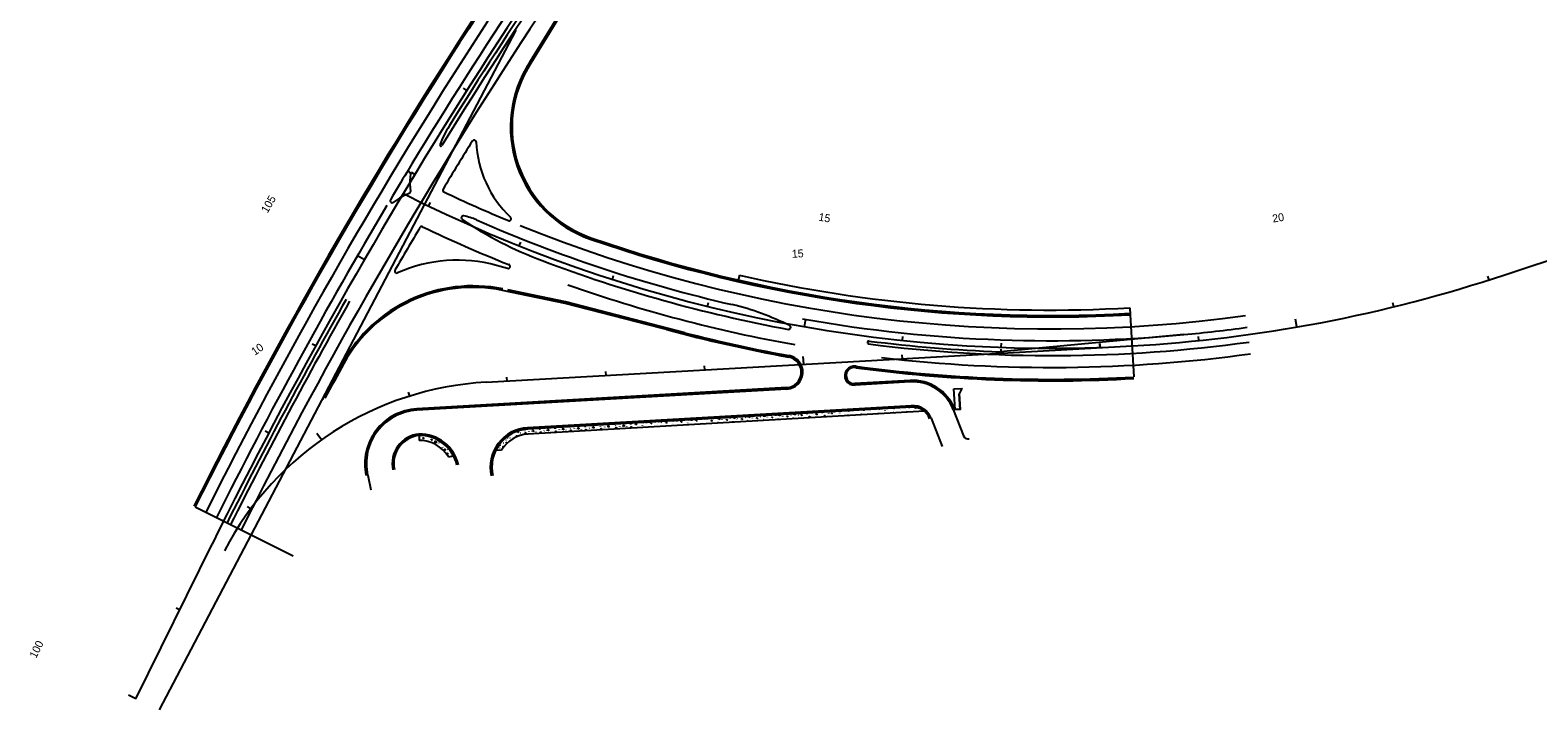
# Model space of a CAD drawing. Extents: x 2339272 to 2351734, y 366540 to 375057.
# Drawn here: x 2345285 to 2346808, y 366762 to 367449 of the extents above; entities that cross this region are included whole.
import ezdxf

# ---------------------------------------------------------------- set-up
doc = ezdxf.new("R2010")
doc.units = 0
for name, color, linetype in [('RD_HC_Cl', 7, 'Continuous'), ('RD_HC_CL_Rel', 7, 'Continuous'), ('RD_HC_Data_Tic', 7, 'Continuous'), ('RD_HC_Data_Tic_Rel', 7, 'Continuous'), ('RD_HC_TX_Rel_Sta50', 7, 'Continuous'), ('RD_HC_TX_Sta50', 7, 'Continuous'), ('RD_PD_Final_LnLine', 7, 'Continuous'), ('RD_PD_Final_TrvlWay', 7, 'Continuous'), ('RD_PD_FOC', 7, 'Continuous'), ('RD_PD_SW', 7, 'Continuous')]:
    doc.layers.add(name, color=color, linetype=linetype)

msp = doc.modelspace()

# ---------------------------------------------------------------- linework, layer by layer
at = {"layer": 'RD_HC_Cl'}
for p, q in [((2345775.2, 367448.5), (2345415, 366761.9)), ((2345775.2, 367448.5), (2345415, 366761.9)), ((2345775.2, 367448.5), (2345415, 366761.9)), ((2345775.2, 367448.5), (2345415, 366761.9)), ((2346774.2, 367201.5), (2347080, 367303.2)), ((2345745.3, 367092.9), (2346397.7, 367129.6)), ((2345391.2, 366773.2), (2345468.3, 366929.3))]:
    msp.add_line(p, q, dxfattribs=at)
for centre, radius, start, end in [((2349947, 364715.5), 4996, 141.0938, 153.6971), ((2346316.3, 368577.7), 1450.4, 273.2156, 288.4001), ((2345763.2, 366774.4), 319, 93.2156, 152.2947)]:
    msp.add_arc(centre, radius, start, end, dxfattribs=at)
at = {"layer": 'RD_HC_CL_Rel'}
msp.add_arc((2346316.3, 368577.7), 1450.4, 243.1643, 273.2156, dxfattribs=at)
at = {"layer": 'RD_HC_Data_Tic'}
for p, q in [((2345725.7, 367387.6), (2345722.3, 367389.8)), ((2345673.1, 367302.6), (2345669.7, 367304.7)), ((2345622.2, 367216.5), (2345615.2, 367220.6)), ((2346758.4, 367196.3), (2346757.1, 367200.1)), ((2346662.1, 367169.1), (2346661.2, 367173)), ((2346564.3, 367148.7), (2346562.9, 367156.5)), ((2346465.2, 367135), (2346464.8, 367139)), ((2345573, 367129.5), (2345569.5, 367131.4)), ((2346265.7, 367122.2), (2346265.4, 367126.2)), ((2346365.5, 367127.8), (2346365.3, 367131.8)), ((2345966.1, 367105.4), (2345965.9, 367109.4)), ((2346066, 367111), (2346065.5, 367119)), ((2346165.8, 367116.6), (2346165.6, 367120.6)), ((2345766.5, 367094.1), (2345766.2, 367098.1)), ((2345866.3, 367099.7), (2345866.1, 367103.7)), ((2345668, 367078.9), (2345666.8, 367082.7)), ((2345525.5, 367041.5), (2345522, 367043.3)), ((2345578.7, 367034.7), (2345574.1, 367041.2)), ((2345507.4, 366965.1), (2345504.2, 366967.5)), ((2345479.9, 366952.5), (2345476.3, 366954.3)), ((2345435.5, 366862.9), (2345431.9, 366864.7)), ((2345391.2, 366773.2), (2345384, 366776.8))]:
    msp.add_line(p, q, dxfattribs=at)
at = {"layer": 'RD_HC_Data_Tic_Rel'}
for p, q in [((2345687.1, 367270.9), (2345688.9, 367274.5)), ((2345778.6, 367230.7), (2345780.1, 367234.4)), ((2345872.7, 367196.8), (2345873.9, 367200.6)), ((2345968.9, 367169.5), (2345969.9, 367173.4)), ((2346066.7, 367149), (2346068.1, 367156.8)), ((2346165.8, 367135.2), (2346166.2, 367139.1)), ((2346265.5, 367128.2), (2346265.7, 367132.2)), ((2346365.5, 367128.2), (2346365.4, 367132.1))]:
    msp.add_line(p, q, dxfattribs=at)
at = {"layer": 'RD_PD_Final_LnLine'}
for p, q in [((2345789.2, 367416.2), (2345867.8, 367544)), ((2345825.4, 367174), (2345767, 367186.1)), ((2345945.8, 367142.9), (2345825.4, 367174)), ((2346173.5, 367093.2), (2346117.9, 367090)), ((2346049.1, 367086), (2345675.1, 367064.5)), ((2346174.9, 367069.2), (2345787.1, 367046.9)), ((2346217, 367065.3), (2346227.4, 367038.7)), ((2346194.7, 367056.6), (2346205.9, 367027.9)), ((2345625.5, 366999.1), (2345628.7, 366984.3)), ((2345550.2, 366917.3), (2345451.2, 366966.8))]:
    msp.add_line(p, q, dxfattribs=at)
for points in [[(2345668.7, 367303.5), (2345668.2, 367296.8), (2345668.1, 367293.1), (2345668.3, 367289.4), (2345668.7, 367285.7)], [(2345667.5, 367283.6), (2345664.3, 367282.3), (2345660.9, 367280.7), (2345657.7, 367278.9), (2345654.5, 367276.9), (2345651.4, 367274.6)]]:
    msp.add_lwpolyline(points, dxfattribs=at)
for centre, radius, start, end in [((2349947, 364715.5), 5028, 141.0938, 153.3996), ((2349947, 364715.5), 5016, 141.0938, 153.4055), ((2349947, 364715.5), 4976, 141.0938, 153.4002), ((2349947, 364715.5), 5004, 144.1409, 148.8707), ((2345889.8, 367350.8), 120, 146.9941, 250.83), ((2349947, 364715.5), 5004, 149.2865, 153.4055), ((2346316.3, 368577.7), 1430.9, 247.9629, 277.8677), ((2346316.3, 368577.7), 1418.9, 250.83, 273.2156), ((2345731.6, 367040.2), 150, 78.3222, 151.1242), ((2346316.3, 368577.7), 1469.9, 250.5817, 259.838), ((2346316.3, 368577.7), 1442.9, 259.9604, 267.9572), ((2346316.3, 368577.7), 1481.9, 254.8096, 259.6918), ((2346316.3, 368577.7), 1442.9, 267.9572, 275.3139), ((2349947, 364715.5), 4964, 151.1242, 151.6138), ((2346048.1, 367103), 17, 273.295, 79.6918), ((2346117, 367099.6), 9.61, 79.003, 275.1081), ((2346316.3, 368577.7), 1481.9, 262.3405, 273.2156), ((2346316.3, 368577.7), 1469.9, 263.2921, 277.8677), ((2346176, 367049.3), 44, 21.3855, 93.295), ((2345678.2, 367010.6), 54, 93.295, 192.3286), ((2346176, 367049.3), 20, 21.3855, 93.295), ((2345680.3, 367010.7), 30, 95.7625, 192.3286), ((2345678.1, 367000.6), 40, 12.6698, 91.1581), ((2345789.4, 367007), 40, 93.295, 192.6698)]:
    msp.add_arc(centre, radius, start, end, dxfattribs=at)
at = {"layer": 'RD_PD_Final_TrvlWay'}
for p, q in [((2345766.8, 367207.9), (2345755.8, 367210.9)), ((2346395.9, 367161.1), (2346399.5, 367098.2)), ((2346450, 367141), (2346264.3, 367123.7))]:
    msp.add_line(p, q, dxfattribs=at)
for centre, radius, start, end in [((2349947, 364715.5), 4992, 144.1121, 148.1246), ((2349947, 364715.5), 4988, 144.1121, 148.3622), ((2345792.4, 367298.2), 100, 147.742, 159.7908), ((2349947, 364715.5), 4964, 148.1282, 148.7856), ((2345733.1, 367335.5), 2, 2.3688, 148.1282), ((2345699.5, 367332.4), 1, 159.7908, 328.3622), ((2345846.1, 367340.2), 111, 182.3688, 226.6168), ((2349947, 364715.5), 5004, 148.84, 149.2061), ((2345666.7, 367303.6), 2, 355.4391, 148.84), ((2345650.2, 367276.2), 2, 149.2061, 306.5069), ((2345666.7, 367285.4), 2, 291.356, 6.6707), ((2345703.4, 367287), 2, 148.7856, 244.5967), ((2346316.3, 368577.7), 1430.9, 244.5967, 247.4525), ((2345722.1, 367259), 2, 79.0993, 236.2521), ((2345711.2, 367202), 60, 66.255, 79.0993), ((2349947, 364715.5), 4964, 149.3076, 149.8844), ((2345680.1, 367248.2), 2, 64.4267, 149.3076), ((2346316.3, 368577.7), 1471.9, 244.4267, 248.1316), ((2345943.2, 367589.9), 400, 236.2521, 249.308), ((2346316.3, 368577.7), 1442.9, 246.255, 257.0838), ((2345768.4, 367258), 2, 247.4525, 46.6168), ((2345716.5, 367066.2), 150, 74.8096, 113.9269), ((2346316.3, 368577.7), 1455.9, 249.308, 259.4801), ((2345654.8, 367205.1), 2, 149.8844, 293.9269), ((2345767.4, 367209.9), 2, 254.8096, 68.1316), ((2349947, 364715.5), 4992, 150.4616, 153.4055), ((2349947, 364715.5), 4988, 150.4616, 153.4055), ((2345929.6, 366906.7), 272.3, 63.3299, 76.3521), ((2346050.9, 367148.3), 2, 259.4801, 63.3299), ((2346316.3, 368577.7), 1442.9, 275.3139, 277.8677), ((2346131.8, 367133.1), 1.5, 82.7196, 172.6606), ((2346131.8, 367133.1), 1.5, 172.6606, 262.7196), ((2346316.3, 368577.7), 1457.9, 262.7196, 277.8677), ((2346316.3, 368577.7), 1454.9, 262.7196, 267.9499), ((2346232.1, 367040.5), 5, 201.3855, 282.6674)]:
    msp.add_arc(centre, radius, start, end, dxfattribs=at)
at = {"layer": 'RD_PD_FOC'}
for p, q in [((2345790.5, 367415.4), (2345869, 367543.2)), ((2345825.1, 367172.5), (2345761.6, 367185.6)), ((2345945.5, 367141.4), (2345825, 367172.5)), ((2346173.4, 367094.7), (2346117.8, 367091.5)), ((2346049, 367087.5), (2345675.1, 367066)), ((2346175, 367067.7), (2345787.2, 367045.4))]:
    msp.add_line(p, q, dxfattribs=at)
for centre, radius, start, end in [((2349947, 364715.5), 5029.5, 141.0938, 153.3986), ((2345889.8, 367350.8), 118.5, 146.9941, 250.83), ((2346316.3, 368577.7), 1417.4, 250.83, 273.2155), ((2345731.6, 367040.2), 148.5, 78.3222, 151.1242), ((2346316.3, 368577.7), 1483.4, 254.8096, 259.6918), ((2349947, 364715.5), 4962.5, 151.1242, 151.5864), ((2346048.1, 367103), 15.5, 273.295, 79.6918), ((2346117, 367099.6), 8.11, 79.003, 275.1081), ((2346316.3, 368577.7), 1483.4, 262.3405, 273.2156), ((2346176, 367049.3), 45.5, 21.3855, 93.295), ((2345678.2, 367010.6), 55.5, 93.295, 192.3286), ((2346176, 367049.3), 18.5, 21.3855, 93.295), ((2345680.3, 367010.7), 28.5, 95.7625, 192.3286), ((2345678.1, 367000.6), 38.5, 12.6698, 91.1581), ((2345789.4, 367007), 38.5, 93.295, 192.6698)]:
    msp.add_arc(centre, radius, start, end, dxfattribs=at)
at = {"layer": 'RD_PD_SW'}
for p, q in [((2346001, 367201.1), (2345999.5, 367194.6)), ((2346395.5, 367168.1), (2346395.9, 367161.1)), ((2346217.7, 367086.1), (2346225.7, 367086.5)), ((2346218.9, 367065.3), (2346217.7, 367086.1)), ((2346225.7, 367086.5), (2346223, 367081.1)), ((2346223.9, 367065.5), (2346223, 367081.1)), ((2346187.9, 367063.5), (2345787.4, 367040.4)), ((2346083.8, 367062.1), (2346083.9, 367062.5)), ((2346111, 367063.6), (2346111.1, 367064.1)), ((2346117.7, 367062.6), (2346117.8, 367062.8)), ((2346126.2, 367064.5), (2346126.4, 367064.9)), ((2346133, 367063.5), (2346133.1, 367063.7)), ((2346141.5, 367065.4), (2346141.7, 367065.8)), ((2346148.3, 367064.3), (2346148.3, 367064.6)), ((2346154.3, 367062.7), (2346154.4, 367062.5)), ((2346156.4, 367062.7), (2346156.6, 367062.6)), ((2346156.8, 367066.3), (2346156.9, 367066.7)), ((2346163.5, 367065.2), (2346163.6, 367065.5)), ((2346169.6, 367063.6), (2346169.7, 367063.4)), ((2346171.7, 367063.6), (2346171.8, 367063.5)), ((2346172, 367067.1), (2346172.2, 367067.6)), ((2346178.8, 367066.1), (2346178.9, 367066.3)), ((2346184.9, 367064.4), (2346185, 367064.3)), ((2346223.9, 367065.5), (2346218.9, 367065.3)), ((2345845.5, 367047.5), (2345845.6, 367047.7)), ((2345860.7, 367048.3), (2345860.8, 367048.6)), ((2345865, 367047.5), (2345865.1, 367047.7)), ((2345876, 367049.2), (2345876.1, 367049.5)), ((2345880.3, 367048.3), (2345880.4, 367048.6)), ((2345886.9, 367048), (2345887, 367047.8)), ((2345891.3, 367050.1), (2345891.4, 367050.4)), ((2345903, 367048.9), (2345903, 367049.2)), ((2345903.6, 367051.9), (2345903.7, 367052.1)), ((2345904.2, 367052.2), (2345903.7, 367051.9)), ((2345906.9, 367051.7), (2345906.9, 367051.4)), ((2345918.2, 367049.8), (2345918.3, 367050)), ((2345918.9, 367052.8), (2345918.9, 367053)), ((2345919.4, 367053), (2345918.9, 367052.8)), ((2345922.1, 367052.5), (2345922.2, 367052.3)), ((2345933.5, 367050.7), (2345933.6, 367050.9)), ((2345934.2, 367053.6), (2345934.2, 367053.9)), ((2345934.7, 367053.9), (2345934.2, 367053.6)), ((2345937.4, 367053.4), (2345937.4, 367053.2)), ((2345948.8, 367051.5), (2345948.9, 367051.8)), ((2345949.4, 367054.5), (2345949.5, 367054.8)), ((2345950, 367054.8), (2345949.5, 367054.5)), ((2345952.7, 367054.3), (2345952.7, 367054)), ((2345964, 367052.4), (2345964.1, 367052.7)), ((2345964.7, 367055.4), (2345964.7, 367055.6)), ((2345965, 367055.5), (2345964.7, 367055.4)), ((2345979.4, 367052.4), (2345979.5, 367052.7)), ((2345980.1, 367055.4), (2345980.1, 367055.5)), ((2345980.2, 367055.9), (2345980.2, 367056.5)), ((2345983.4, 367055.2), (2345983.4, 367054.9)), ((2345992, 367056.4), (2345992.1, 367056.6)), ((2345994.7, 367053.3), (2345994.8, 367053.6)), ((2345995.4, 367056.3), (2345995.5, 367057.4)), ((2345998.6, 367056.1), (2345998.7, 367055.8)), ((2346007.3, 367057.3), (2346007.4, 367057.5)), ((2346010, 367054.2), (2346010.1, 367054.4)), ((2346010.6, 367057.2), (2346010.7, 367058.3)), ((2346013.9, 367056.9), (2346013.9, 367056.7)), ((2346022.5, 367058.1), (2346022.6, 367058.4)), ((2346025.2, 367055.1), (2346025.3, 367055.3)), ((2346025.9, 367058), (2346026, 367059.2)), ((2346029.2, 367057.8), (2346029.2, 367057.6)), ((2346037.8, 367059), (2346037.9, 367059.3)), ((2346040.5, 367055.9), (2346040.6, 367056.2)), ((2346041.2, 367058.9), (2346041.3, 367060)), ((2346044.4, 367058.7), (2346044.5, 367058.4)), ((2346053.1, 367059.9), (2346053.2, 367060.1)), ((2346055.8, 367056.8), (2346055.9, 367057.1)), ((2346056.5, 367059.8), (2346056.5, 367060.9)), ((2346060.5, 367059.8), (2346060.6, 367059.6)), ((2346068.5, 367061.3), (2346068.7, 367061.6)), ((2346075.8, 367060.6), (2346075.9, 367060.5)), ((2346091, 367061.5), (2346091.1, 367061.4)), ((2346102.4, 367061.7), (2346102.5, 367061.9)), ((2346108.5, 367060), (2346108.6, 367059.9)), ((2346110.6, 367060.1), (2346110.8, 367059.9)), ((2346123.8, 367060.9), (2346123.9, 367060.8)), ((2346125.9, 367061), (2346126, 367060.8)), ((2346139.1, 367061.8), (2346139.2, 367061.6)), ((2346141.2, 367061.9), (2346141.3, 367061.7)), ((2345677.4, 367039.1), (2345677.4, 367034.1)), ((2345686.5, 367038), (2345686.6, 367038.1)), ((2345686.9, 367038), (2345686.5, 367038)), ((2345690.3, 367031.9), (2345690.4, 367032.1)), ((2345762.4, 367031.8), (2345762.6, 367031.7)), ((2345765.4, 367034.4), (2345765.5, 367034.7)), ((2345766.9, 367036.6), (2345767, 367036.4)), ((2345769, 367036.6), (2345769.2, 367036.5)), ((2345776.1, 367039.1), (2345776.2, 367039.4)), ((2345776.8, 367042.1), (2345776.9, 367043.4)), ((2345780, 367041.9), (2345780.1, 367041.6)), ((2345784.4, 367044), (2345784.5, 367044.2)), ((2345788.7, 367043.1), (2345788.8, 367043.3)), ((2345795.3, 367042.7), (2345795.3, 367042.5)), ((2345799.7, 367044.8), (2345799.8, 367045.1)), ((2345803.9, 367043.9), (2345804, 367044.2)), ((2345810.6, 367043.6), (2345810.6, 367043.4)), ((2345814.9, 367045.7), (2345815, 367046)), ((2345819.2, 367044.8), (2345819.3, 367045.1)), ((2345825.8, 367044.5), (2345825.9, 367044.3)), ((2345830.2, 367046.6), (2345830.3, 367046.8)), ((2345834.5, 367045.7), (2345834.6, 367046)), ((2345841.1, 367045.4), (2345841.2, 367045.1)), ((2345849.7, 367046.6), (2345849.8, 367046.8)), ((2345856.4, 367046.3), (2345856.4, 367046)), ((2345696.9, 367031.6), (2345697, 367031.3)), ((2345699.1, 367027.2), (2345699.2, 367027)), ((2345701.2, 367027.2), (2345701.3, 367027.1)), ((2345701.5, 367030.7), (2345701.6, 367031)), ((2345701.8, 367030.9), (2345701.5, 367030.7)), ((2345706.3, 367024.9), (2345706.4, 367025.1)), ((2345707, 367017.5), (2345712.1, 367018.6)), ((2345760.7, 367024.3), (2345754.8, 367024)), ((2345759, 367026.4), (2345759.1, 367026.6))]:
    msp.add_line(p, q, dxfattribs=at)
msp.add_lwpolyline([(2346217.7, 367086.1), (2346225.7, 367086.5), (2346223, 367081.1), (2346223.9, 367065.5), (2346218.9, 367065.3)], close=True, dxfattribs=at)
for points in [[(2346085, 367062.6), (2346085.1, 367062.3), (2346083.8, 367062.1)], [(2346096.4, 367063.2), (2346096.6, 367063.1), (2346096.2, 367062.9)], [(2346111.6, 367064.1), (2346111.8, 367064), (2346111, 367063.6)], [(2346126.9, 367065), (2346127.1, 367064.8), (2346126.2, 367064.5)], [(2346142.2, 367065.9), (2346142.4, 367065.7), (2346141.5, 367065.4)], [(2346157.4, 367066.7), (2346157.6, 367066.6), (2346156.8, 367066.3)], [(2346172.7, 367067.6), (2346172.9, 367067.5), (2346172, 367067.1)], [(2345837.9, 367045.6), (2345838, 367047.2), (2345839, 367046.2), (2345837.9, 367045.6)], [(2345853.1, 367046.5), (2345853.3, 367048.1), (2345854.3, 367047.1), (2345853.2, 367046.5)], [(2345868.4, 367047.4), (2345868.5, 367049), (2345869.6, 367048), (2345868.4, 367047.4)], [(2345883.7, 367048.2), (2345883.8, 367049.8), (2345884.9, 367048.9), (2345883.7, 367048.3)], [(2345891.5, 367047.2), (2345891.8, 367047.9), (2345892.4, 367047.5), (2345891.5, 367047.2)], [(2345896.2, 367050), (2345896.5, 367050.7), (2345897.1, 367050.3), (2345896.2, 367050)], [(2345911.5, 367050.8), (2345911.8, 367051.5), (2345912.3, 367051.2), (2345911.5, 367050.8)], [(2345926.7, 367051.7), (2345927, 367052.4), (2345927.6, 367052), (2345926.7, 367051.7)], [(2345942, 367052.6), (2345942.3, 367053.3), (2345942.9, 367052.9), (2345942, 367052.6)], [(2345957.3, 367053.5), (2345957.6, 367054.2), (2345958.1, 367053.8), (2345957.3, 367053.5)], [(2345972.7, 367053.5), (2345973, 367054.2), (2345973.5, 367053.8), (2345972.7, 367053.5)], [(2345980.7, 367056.6), (2345981.3, 367056), (2345980.1, 367055.4)], [(2345987.9, 367054.4), (2345988.2, 367055.1), (2345988.8, 367054.7), (2345987.9, 367054.4)], [(2345996, 367057.4), (2345996.6, 367056.9), (2345995.4, 367056.3)], [(2346003.2, 367055.2), (2346003.5, 367056), (2346004.1, 367055.6), (2346003.2, 367055.2)], [(2346011.3, 367058.3), (2346011.8, 367057.8), (2346010.7, 367057.2)], [(2346018.5, 367056.1), (2346018.8, 367056.8), (2346019.3, 367056.4), (2346018.5, 367056.1)], [(2346026.5, 367059.2), (2346027.1, 367058.7), (2346025.9, 367058.1)], [(2346033.7, 367057), (2346034, 367057.7), (2346034.6, 367057.3), (2346033.7, 367057)], [(2346041.8, 367060.1), (2346042.4, 367059.5), (2346041.2, 367058.9)], [(2346049, 367057.9), (2346049.3, 367058.6), (2346049.9, 367058.2), (2346049, 367057.9)], [(2346057.1, 367061), (2346057.6, 367060.4), (2346056.5, 367059.8)], [(2346063.4, 367059.2), (2346063.7, 367059.9), (2346064.3, 367059.5), (2346063.4, 367059.2)], [(2346069.7, 367061.7), (2346069.8, 367061.4), (2346068.5, 367061.3)], [(2346071.6, 367057.7), (2346071.9, 367058.4), (2346072.5, 367058), (2346071.6, 367057.7)], [(2346078.7, 367060.1), (2346079, 367060.8), (2346079.6, 367060.4), (2346078.7, 367060.1)], [(2346086.9, 367058.6), (2346087.2, 367059.3), (2346087.8, 367058.9), (2346086.9, 367058.6)], [(2346094, 367061), (2346094.3, 367061.7), (2346094.8, 367061.3), (2346094, 367061)], [(2345681.4, 367035.9), (2345681.7, 367036.6), (2345682.3, 367036.3), (2345681.4, 367035.9)], [(2345689.6, 367034.4), (2345689.9, 367035.1), (2345690.5, 367034.7), (2345689.6, 367034.4)], [(2345693.7, 367031.8), (2345693.8, 367033.4), (2345694.9, 367032.4), (2345693.7, 367031.8)], [(2345765.4, 367031.3), (2345765.7, 367032), (2345766.3, 367031.6), (2345765.4, 367031.3)], [(2345777.1, 367043.5), (2345778, 367042.7), (2345776.8, 367042.1)], [(2345784.6, 367041), (2345784.9, 367041.8), (2345785.5, 367041.4), (2345784.6, 367041)], [(2345792.1, 367043), (2345792.2, 367044.6), (2345793.2, 367043.6), (2345792.1, 367043)], [(2345799.9, 367041.9), (2345800.2, 367042.6), (2345800.8, 367042.3), (2345799.9, 367041.9)], [(2345807.3, 367043.8), (2345807.5, 367045.4), (2345808.5, 367044.5), (2345807.4, 367043.9)], [(2345815.2, 367042.8), (2345815.5, 367043.5), (2345816, 367043.1), (2345815.2, 367042.8)], [(2345822.6, 367044.7), (2345822.7, 367046.3), (2345823.8, 367045.4), (2345822.6, 367044.7)], [(2345830.4, 367043.7), (2345830.7, 367044.4), (2345831.3, 367044), (2345830.4, 367043.7)], [(2345845.7, 367044.6), (2345846, 367045.3), (2345846.6, 367044.9), (2345845.7, 367044.6)], [(2345861, 367045.4), (2345861.3, 367046.2), (2345861.8, 367045.8), (2345861, 367045.4)], [(2345876.2, 367046.3), (2345876.5, 367047), (2345877.1, 367046.7), (2345876.2, 367046.3)], [(2345702.6, 367023.9), (2345703.3, 367025.4), (2345703.9, 367024.1), (2345702.6, 367023.9)], [(2345705.7, 367020.3), (2345706, 367021.1), (2345706.6, 367020.7), (2345705.7, 367020.3)], [(2345755.3, 367025), (2345755.8, 367024.7), (2345755, 367024.4)], [(2345758.3, 367028.9), (2345758.6, 367029.6), (2345759.2, 367029.2), (2345758.3, 367028.9)], [(2345762.4, 367026.9), (2345762.5, 367027.9), (2345762.9, 367027.5)]]:
    msp.add_lwpolyline(points, dxfattribs=at)
for centre, radius, start, end in [((2346314.9, 368577.9), 1412.1, 257.1583, 273.2751), ((2345678.1, 367000.6), 33.5, 30.3687, 91.1581), ((2345789.4, 367007), 33.5, 93.295, 148.7964)]:
    msp.add_arc(centre, radius, start, end, dxfattribs=at)

# ---------------------------------------------------------------- texts
at = {"layer": 'RD_HC_TX_Rel_Sta50'}
msp.add_text('15', height=8, rotation=350.0908, dxfattribs=at).set_placement((2346080.5, 367256.2))
at = {"layer": 'RD_HC_TX_Sta50'}
for s, rotation, p in [('105', 59.9591, (2345524.3, 367263.1)), ('20', 9.8428, (2346540.1, 367254.1)), ('15', 3.2156, (2346054.2, 367218.5)), ('10', 35.3268, (2345511.5, 367119.5)), ('100', 63.6971, (2345290.5, 366813.3))]:
    msp.add_text(s, height=8, rotation=rotation, dxfattribs=at).set_placement(p)

doc.saveas('drawing.dxf')
